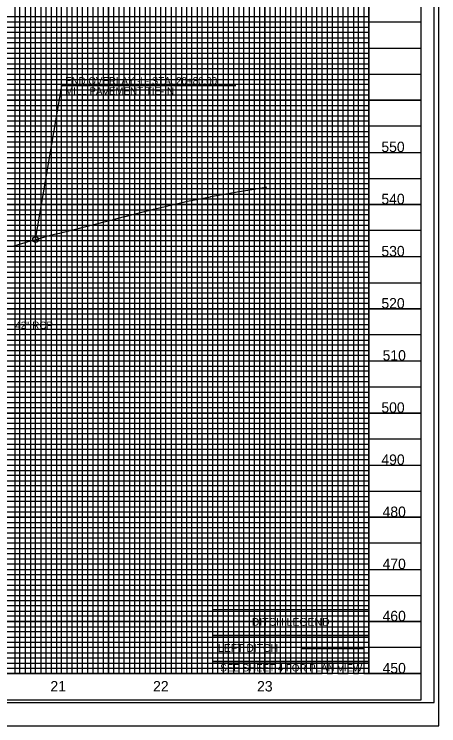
# Model space of a CAD drawing. Extents: x 572694 to 574378, y -52955 to -51855.
# Drawn here: x 573971 to 574378, y -52955 to -52273 of the extents above; entities that cross this region are included whole.
import ezdxf

# ---------------------------------------------------------------- set-up
doc = ezdxf.new("R2010")
doc.units = 0
for name, color, linetype in [('Exist Profile Cell', 7, 'Continuous'), ('Exist Vertical Profile Ground Line', 7, 'Continuous'), ('Exist Vertical Profile Horizontal Axis Label Major', 7, 'Continuous'), ('Exist Vertical Profile Vertical Axis Label', 7, 'Continuous'), ('Prop Drainage Structure Box Reinforced Concrete Label', 7, 'Continuous'), ('Prop Grid Mask', 7, 'Continuous'), ('Prop PFL Ditch Label CELL', 7, 'Continuous'), ('Prop Vertical Profile Curve Label', 7, 'Continuous'), ('Sheet Cutting Line CELL', 7, 'Continuous'), ('Sheet DOT Grid CELL', 7, 'Continuous'), ('Sheet Plot Border Inside CELL', 7, 'Continuous'), ('Sheet Plot Border Outside CELL', 7, 'Continuous'), ('Sheet Profile CELL', 7, 'Continuous'), ('Sheet Profile Grid Major CELL', 7, 'Continuous'), ('Sheet Profile Grid Middle CELL', 7, 'Continuous'), ('Sheet Profile Grid Minor CELL', 7, 'Continuous')]:
    doc.layers.add(name, color=color, linetype=linetype)

msp = doc.modelspace()

# ---------------------------------------------------------------- linework, layer by layer
at = {"layer": 'Exist Profile Cell'}
msp.add_line((572911.5, -52905.14), (574213.46, -52905.14), dxfattribs=at)
at = {"layer": 'Exist Vertical Profile Ground Line'}
for points in [[(574076.26, -52466.95), (574104.58, -52459.67), (574104.96, -52459.58), (574134.59, -52452.66), (574137.05, -52452.09), (574137.35, -52452.02), (574159.22, -52447.7), (574159.85, -52447.59), (574186.8, -52442.72), (574187.22, -52442.65), (574212.87, -52438.42), (574213.46, -52438.29)], [(573969.33, -52495.16), (573973.11, -52494.07), (573976.88, -52492.98), (573980.66, -52491.89), (573984.43, -52490.79), (573988.21, -52489.7), (573991.98, -52488.61), (573995.76, -52487.51), (573999.53, -52486.42), (574003.31, -52485.33), (574003.63, -52485.23), (574007.08, -52484.38), (574010.86, -52483.44), (574014.63, -52482.51), (574017.1, -52481.9), (574017.74, -52481.73), (574018.41, -52481.57), (574022.18, -52480.61), (574025.96, -52479.66), (574029.73, -52478.7), (574033.51, -52477.75), (574037.28, -52476.79), (574041.06, -52475.84), (574044.83, -52474.88), (574048.61, -52473.92), (574052.38, -52472.96), (574056.16, -52472), (574057.46, -52471.67), (574059.93, -52471.04), (574063.71, -52470.09), (574067.48, -52469.13), (574068.35, -52468.92), (574075.54, -52467.13), (574076.26, -52466.95)]]:
    msp.add_lwpolyline(points, dxfattribs=at)
at = {"layer": 'Prop Grid Mask'}
for points in [[(574161.5, -52843.6), (574311.5, -52843.6), (574311.5, -52868.6), (574161.5, -52868.6)], [(574161.5, -52868.6), (574311.5, -52868.6), (574311.5, -52893.6), (574161.5, -52893.6)], [(574161.5, -52893.6), (574311.5, -52893.6), (574311.5, -52905.14), (574161.5, -52905.14)]]:
    msp.add_lwpolyline(points, close=True, dxfattribs=at)
at = {"layer": 'Prop PFL Ditch Label CELL'}
msp.add_line((574247.05, -52880.9), (574307.05, -52880.9), dxfattribs=at)
at = {"layer": 'Prop Vertical Profile Curve Label'}
for p in [(573991.5, -52488.75), (574183.57, -52341.47)]:
    msp.add_line(p, (574016.61, -52341.47), dxfattribs=at)
msp.add_circle((573991.5, -52488.75), 2.75, dxfattribs=at)
at = {"layer": 'Sheet Cutting Line CELL'}
msp.add_line((572694.5, -52955.14), (574378.5, -52955.14), dxfattribs=at)
at = {"layer": 'Sheet DOT Grid CELL'}
for p, q in [((574011.5, -51880.14), (574011.5, -52905.14)), ((574061.5, -51880.14), (574061.5, -52905.14)), ((574111.5, -51880.14), (574111.5, -52905.14)), ((574161.5, -52905.14), (574161.5, -52017.69)), ((574211.5, -52905.14), (574211.5, -52041.19)), ((574261.5, -52905.14), (574261.5, -52041.19)), ((574311.5, -52905.14), (574311.5, -52041.19)), ((572861.5, -52305.14), (574361.5, -52305.14)), ((572861.5, -52355.14), (574361.5, -52355.14)), ((572861.5, -52405.14), (574361.5, -52405.14)), ((572861.5, -52455.14), (574361.5, -52455.14)), ((572861.5, -52505.14), (574361.5, -52505.14)), ((572861.5, -52555.14), (574361.5, -52555.14)), ((572861.5, -52605.14), (574361.5, -52605.14)), ((572861.5, -52655.14), (574361.5, -52655.14)), ((572861.5, -52705.14), (574361.5, -52705.14)), ((572861.5, -52755.14), (574361.5, -52755.14)), ((572861.5, -52805.14), (574361.5, -52805.14)), ((572861.5, -52855.14), (574361.5, -52855.14))]:
    msp.add_line(p, q, dxfattribs=at)
at = {"layer": 'Sheet Plot Border Inside CELL'}
msp.add_lwpolyline([(574374, -51877.59), (572707.5, -51877.59), (572707.5, -52932.69), (574374, -52932.69)], close=True, dxfattribs=at)
at = {"layer": 'Sheet Plot Border Outside CELL'}
msp.add_lwpolyline([(574378.5, -51855.14), (572694.5, -51855.14), (572694.5, -52955.14), (574378.5, -52955.14)], close=True, dxfattribs=at)
at = {"layer": 'Sheet Profile CELL'}
msp.add_line((574361.5, -52905.14), (572861.5, -52905.14), dxfattribs=at)
msp.add_lwpolyline([(574361.5, -51880.14), (572861.5, -51880.14), (572861.5, -52930.14), (574361.5, -52930.14)], close=True, dxfattribs=at)
at = {"layer": 'Sheet Profile Grid Major CELL'}
for points in [[(573961.5, -51880.14), (574011.5, -51880.14), (574011.5, -52905.14), (574061.5, -52905.14), (574061.5, -51880.14), (574111.5, -51880.14), (574111.5, -52905.14), (574161.5, -52905.14), (574161.5, -51880.14), (574187.8, -51880.14)], [(574211.5, -52041.19), (574211.5, -52905.14), (574261.5, -52905.14), (574261.5, -52041.19)], [(574311.5, -52041.19), (574311.5, -52905.14), (574361.5, -52905.14)], [(574361.5, -52355.14), (572861.5, -52355.14), (572861.5, -52305.14), (574361.5, -52305.14)], [(574361.5, -52455.14), (572861.5, -52455.14), (572861.5, -52405.14), (574361.5, -52405.14)], [(574361.5, -52555.14), (572861.5, -52555.14), (572861.5, -52505.14), (574361.5, -52505.14)], [(574361.5, -52655.14), (572861.5, -52655.14), (572861.5, -52605.14), (574361.5, -52605.14)], [(574361.5, -52755.14), (572861.5, -52755.14), (572861.5, -52705.14), (574361.5, -52705.14)], [(574361.5, -52855.14), (572861.5, -52855.14), (572861.5, -52805.14), (574361.5, -52805.14)]]:
    msp.add_lwpolyline(points, dxfattribs=at)
at = {"layer": 'Sheet Profile Grid Middle CELL'}
for points in [[(573936.5, -51880.14), (573986.5, -51880.14), (573986.5, -52905.14), (574036.5, -52905.14), (574036.5, -51880.14), (574086.5, -51880.14), (574086.5, -52905.14), (574136.5, -52905.14), (574136.5, -51880.14)], [(574186.5, -52041.19), (574186.5, -52905.14), (574236.5, -52905.14), (574236.5, -52041.19)], [(574286.5, -52041.19), (574286.5, -52905.14)], [(574361.5, -52280.14), (572861.5, -52280.14), (572861.5, -52330.14), (574361.5, -52330.14)], [(574361.5, -52380.14), (572861.5, -52380.14), (572861.5, -52430.14), (574361.5, -52430.14)], [(574361.5, -52480.14), (572861.5, -52480.14), (572861.5, -52530.14), (574361.5, -52530.14)], [(574361.5, -52580.14), (572861.5, -52580.14), (572861.5, -52630.14), (574361.5, -52630.14)], [(574361.5, -52680.14), (572861.5, -52680.14), (572861.5, -52730.14), (574361.5, -52730.14)], [(574361.5, -52780.14), (572861.5, -52780.14), (572861.5, -52830.14), (574361.5, -52830.14)], [(574361.5, -52880.14), (572861.5, -52880.14)]]:
    msp.add_lwpolyline(points, dxfattribs=at)
at = {"layer": 'Sheet Profile Grid Minor CELL'}
for points in [[(573971.5, -51880.14), (573971.5, -52905.14), (573976.5, -52905.14), (573976.5, -51880.14)], [(573981.5, -51880.14), (573981.5, -52905.14), (573991.5, -52905.14), (573991.5, -51880.14)], [(573996.5, -51880.14), (573996.5, -52905.14), (574001.5, -52905.14), (574001.5, -51880.14)], [(574006.5, -51880.14), (574006.5, -52905.14), (574016.5, -52905.14), (574016.5, -51880.14)], [(574021.5, -51880.14), (574021.5, -52905.14), (574026.5, -52905.14), (574026.5, -51880.14)], [(574031.5, -51880.14), (574031.5, -52905.14), (574041.5, -52905.14), (574041.5, -51880.14)], [(574046.5, -51880.14), (574046.5, -52905.14), (574051.5, -52905.14), (574051.5, -51880.14)], [(574056.5, -51880.14), (574056.5, -52905.14), (574066.5, -52905.14), (574066.5, -51880.14)], [(574071.5, -51880.14), (574071.5, -52905.14), (574076.5, -52905.14), (574076.5, -51880.14)], [(574081.5, -51880.14), (574081.5, -52905.14), (574091.5, -52905.14), (574091.5, -51880.14)], [(574096.5, -51880.14), (574096.5, -52905.14), (574101.5, -52905.14), (574101.5, -51880.14)], [(574106.5, -51880.14), (574106.5, -52905.14), (574116.5, -52905.14), (574116.5, -51880.14)], [(574121.5, -51880.14), (574121.5, -52905.14), (574126.5, -52905.14), (574126.5, -51880.14)], [(574131.5, -51880.14), (574131.5, -52905.14), (574141.5, -52905.14), (574141.5, -51880.14)], [(574146.5, -51880.14), (574146.5, -52905.14), (574151.5, -52905.14), (574151.5, -51880.14)], [(574156.5, -51880.14), (574156.5, -52905.14), (574166.5, -52905.14), (574166.5, -52041.19)], [(574171.5, -52041.19), (574171.5, -52905.14), (574176.5, -52905.14), (574176.5, -52041.19)], [(574181.5, -52041.19), (574181.5, -52905.14), (574191.5, -52905.14), (574191.5, -52041.19)], [(574196.5, -52041.19), (574196.5, -52905.14), (574201.5, -52905.14), (574201.5, -52041.19)], [(574206.5, -52041.19), (574206.5, -52905.14), (574216.5, -52905.14), (574216.5, -52041.19)], [(574221.5, -52041.19), (574221.5, -52905.14), (574226.5, -52905.14), (574226.5, -52041.19)], [(574231.5, -52041.19), (574231.5, -52905.14), (574241.5, -52905.14), (574241.5, -52041.19)], [(574246.5, -52041.19), (574246.5, -52905.14)], [(574246.5, -52905.14), (574251.5, -52905.14), (574251.5, -52041.19)], [(574256.5, -52041.19), (574256.5, -52905.14), (574266.5, -52905.14), (574266.5, -52041.19)], [(574271.5, -52041.19), (574271.5, -52905.14), (574276.5, -52905.14), (574276.5, -52041.19)], [(574281.5, -52041.19), (574281.5, -52905.14), (574291.5, -52905.14), (574291.5, -52041.19)], [(574296.5, -52041.19), (574296.5, -52905.14), (574301.5, -52905.14), (574301.5, -52041.19)], [(574306.5, -52041.19), (574306.5, -52905.14), (574316.5, -52905.14)], [(574311.5, -52275.14), (572911.5, -52275.14), (572911.5, -52285.14), (574311.5, -52285.14)], [(574311.5, -52290.14), (572911.5, -52290.14), (572911.5, -52295.14), (574311.5, -52295.14)], [(574311.5, -52300.14), (572911.5, -52300.14), (572911.5, -52310.14), (574311.5, -52310.14)], [(574311.5, -52315.14), (572911.5, -52315.14), (572911.5, -52320.14), (574311.5, -52320.14)], [(574311.5, -52325.14), (572911.5, -52325.14), (572911.5, -52335.14), (574311.5, -52335.14)], [(574311.5, -52340.14), (572911.5, -52340.14), (572911.5, -52345.14), (574311.5, -52345.14)], [(574311.5, -52350.14), (572911.5, -52350.14), (572911.5, -52360.14), (574311.5, -52360.14)], [(574311.5, -52365.14), (572911.5, -52365.14), (572911.5, -52370.14), (574311.5, -52370.14)], [(574311.5, -52375.14), (572911.5, -52375.14), (572911.5, -52385.14), (574311.5, -52385.14)], [(574311.5, -52390.14), (572911.5, -52390.14), (572911.5, -52395.14), (574311.5, -52395.14)], [(574311.5, -52400.14), (572911.5, -52400.14)], [(572911.5, -52410.14), (574311.5, -52410.14)], [(574311.5, -52415.14), (572911.5, -52415.14), (572911.5, -52420.14), (574311.5, -52420.14)], [(574311.5, -52425.14), (572911.5, -52425.14), (572911.5, -52435.14), (574311.5, -52435.14)], [(574311.5, -52440.14), (572911.5, -52440.14), (572911.5, -52445.14), (574311.5, -52445.14)], [(574311.5, -52450.14), (572911.5, -52450.14), (572911.5, -52460.14), (574311.5, -52460.14)], [(574311.5, -52465.14), (572911.5, -52465.14), (572911.5, -52470.14), (574311.5, -52470.14)], [(574311.5, -52475.14), (572911.5, -52475.14), (572911.5, -52485.14), (574311.5, -52485.14)], [(574311.5, -52490.14), (572911.5, -52490.14), (572911.5, -52495.14), (574311.5, -52495.14)], [(574311.5, -52500.14), (572911.5, -52500.14), (572911.5, -52510.14), (574311.5, -52510.14)], [(574311.5, -52515.14), (572911.5, -52515.14), (572911.5, -52520.14), (574311.5, -52520.14)], [(574311.5, -52525.14), (572911.5, -52525.14), (572911.5, -52535.14), (574311.5, -52535.14)], [(574311.5, -52540.14), (572911.5, -52540.14), (572911.5, -52545.14), (574311.5, -52545.14)], [(574311.5, -52550.14), (572911.5, -52550.14), (572911.5, -52560.14), (574311.5, -52560.14)], [(574311.5, -52565.14), (572911.5, -52565.14), (572911.5, -52570.14), (574311.5, -52570.14)], [(574311.5, -52575.14), (572911.5, -52575.14), (572911.5, -52585.14), (574311.5, -52585.14)], [(574311.5, -52590.14), (572911.5, -52590.14), (572911.5, -52595.14), (574311.5, -52595.14)], [(574311.5, -52600.14), (572911.5, -52600.14), (572911.5, -52610.14), (574311.5, -52610.14)], [(574311.5, -52615.14), (572911.5, -52615.14), (572911.5, -52620.14), (574311.5, -52620.14)], [(574311.5, -52625.14), (572911.5, -52625.14), (572911.5, -52635.14), (574311.5, -52635.14)], [(574311.5, -52640.14), (572911.5, -52640.14), (572911.5, -52645.14), (574311.5, -52645.14)], [(574311.5, -52650.14), (572911.5, -52650.14), (572911.5, -52660.14), (574311.5, -52660.14)], [(574311.5, -52665.14), (572911.5, -52665.14), (572911.5, -52670.14), (574311.5, -52670.14)], [(574311.5, -52675.14), (572911.5, -52675.14), (572911.5, -52685.14), (574311.5, -52685.14)], [(574311.5, -52690.14), (572911.5, -52690.14), (572911.5, -52695.14), (574311.5, -52695.14)], [(574311.5, -52700.14), (572911.5, -52700.14)], [(572911.5, -52710.14), (574311.5, -52710.14)], [(574311.5, -52715.14), (572911.5, -52715.14), (572911.5, -52720.14), (574311.5, -52720.14)], [(574311.5, -52725.14), (572911.5, -52725.14)], [(572911.5, -52735.14), (574311.5, -52735.14)], [(574311.5, -52740.14), (572911.5, -52740.14), (572911.5, -52745.14), (574311.5, -52745.14)], [(574311.5, -52750.14), (572911.5, -52750.14), (572911.5, -52760.14), (574311.5, -52760.14)], [(574311.5, -52765.14), (572911.5, -52765.14), (572911.5, -52770.14), (574311.5, -52770.14)], [(574311.5, -52775.14), (572911.5, -52775.14), (572911.5, -52785.14), (574311.5, -52785.14)], [(574311.5, -52790.14), (572911.5, -52790.14), (572911.5, -52795.14), (574311.5, -52795.14)], [(574311.5, -52800.14), (572911.5, -52800.14), (572911.5, -52810.14), (574311.5, -52810.14)], [(574311.5, -52815.14), (572911.5, -52815.14), (572911.5, -52820.14), (574311.5, -52820.14)], [(574311.5, -52825.14), (572911.5, -52825.14), (572911.5, -52835.14), (574311.5, -52835.14)], [(574311.5, -52840.14), (572911.5, -52840.14), (572911.5, -52845.14), (574311.5, -52845.14)], [(574311.5, -52850.14), (572911.5, -52850.14), (572911.5, -52860.14), (574311.5, -52860.14)], [(574311.5, -52865.14), (572911.5, -52865.14), (572911.5, -52870.14), (574311.5, -52870.14)], [(574311.5, -52875.14), (572911.5, -52875.14), (572911.5, -52885.14), (574311.5, -52885.14)], [(574311.5, -52890.14), (572911.5, -52890.14), (572911.5, -52895.14), (574311.5, -52895.14)], [(574311.5, -52900.14), (572911.5, -52900.14)]]:
    msp.add_lwpolyline(points, dxfattribs=at)

# ---------------------------------------------------------------- texts
at = {"layer": 'Exist Vertical Profile Horizontal Axis Label Major'}
for s, height, p in [('SEE SHEET 4 FOR PLAN VIEW', 7, (574168.75, -52903)), ('21', 10, (574005.72, -52922.24)), ('22', 10, (574104.27, -52922.24)), ('23', 10, (574204.1, -52922.24))]:
    msp.add_text(s, height=height, dxfattribs=at).set_placement(p)
at = {"layer": 'Exist Vertical Profile Vertical Axis Label'}
for s, p in [('550', (574323.42, -52404.89)), ('540', (574323.42, -52454.89)), ('530', (574323.42, -52504.89)), ('520', (574323.42, -52554.89)), ('510', (574324.61, -52604.89)), ('500', (574323.42, -52654.89)), ('490', (574323.42, -52704.89)), ('480', (574324.55, -52754.89)), ('470', (574324.55, -52804.89)), ('460', (574324.55, -52854.89)), ('450', (574324.55, -52904.89))]:
    msp.add_text(s, height=10, dxfattribs=at).set_placement(p)
at = {"layer": 'Prop Drainage Structure Box Reinforced Concrete Label'}
msp.add_text('42" RCP', height=7, dxfattribs=at).set_placement((573971.99, -52574.48))
at = {"layer": 'Prop PFL Ditch Label CELL'}
for s, height, p in [('DITCH LEGEND', 7.5, (574199, -52859.25)), ('LEFT DITCH', 7.485, (574166.5, -52884.3))]:
    msp.add_text(s, height=height, dxfattribs=at).set_placement(p)
at = {"layer": 'Prop Vertical Profile Curve Label'}
for s, p in [('END OVERLAY -L- STA. 20+80.00', (574019.78, -52339.97)), ('MILL PAVEMENT TIE-IN', (574019.78, -52349.77))]:
    msp.add_text(s, height=7, rotation=360, dxfattribs=at).set_placement(p)

doc.saveas('drawing.dxf')
